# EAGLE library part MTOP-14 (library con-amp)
AMP connector
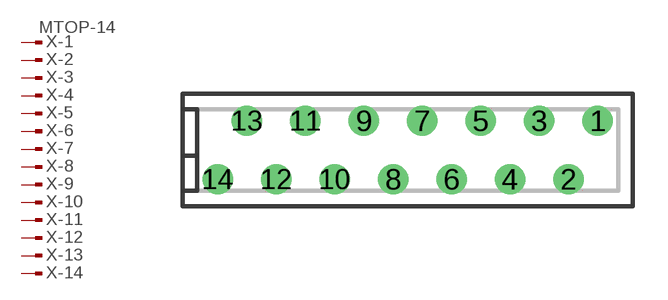
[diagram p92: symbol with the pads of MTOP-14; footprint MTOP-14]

Designator prefix X; gates -1=PIN-MV -2=PIN-M -3=PIN-M -4=PIN-M -5=PIN-M -6=PIN-M -7=PIN-M -8=PIN-M -9=PIN-M -10=PIN-M -11=PIN-M -12=PIN-M -13=PIN-M -14=PIN-M

## MTOP-14 (OC_FARNELL: unknown; OC_NEWARK: unknown)  [MTOP-14]
1  -1:1  pas
2  -2:1  pas
3  -3:1  pas
4  -4:1  pas
5  -5:1  pas
6  -6:1  pas
7  -7:1  pas
8  -8:1  pas
9  -9:1  pas
10  -10:1  pas
11  -11:1  pas
12  -12:1  pas
13  -13:1  pas
14  -14:1  pas

## Footprint MTOP-14 (pad centres in mm)
AMP connector
drill 0.813 round: 1 8.255,1.27; 2 6.985,-1.27; 3 5.715,1.27; 4 4.445,-1.27; 5 3.175,1.27; 6 1.905,-1.27; 7 0.635,1.27; 8 -0.635,-1.27; 9 -1.905,1.27; 10 -3.175,-1.27; 11 -4.445,1.27; 12 -5.715,-1.27; 13 -6.985,1.27; 14 -8.255,-1.27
